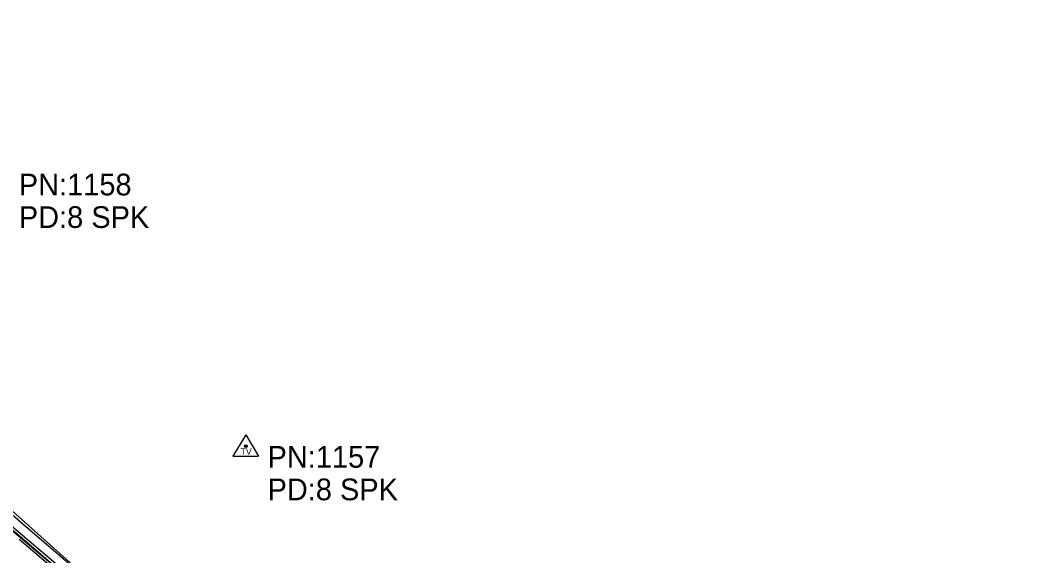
# Model space of a CAD drawing. Extents: x 878399 to 889864, y 1564003 to 1567413.
# Drawn here: x 884685 to 884917.5, y 1565562 to 1565685.6 of the extents above; entities that cross this region are included whole.
import ezdxf

# ---------------------------------------------------------------- set-up
doc = ezdxf.new("R2010")
doc.units = 0
for name, color, linetype in [('S_DITCHLINE', 7, 'Continuous'), ('S_EDGE_CONCRETE', 7, 'Continuous'), ('S_EDGE_PAVEMENT', 7, 'Continuous'), ('S_SECONDARY_CTL', 7, 'Continuous'), ('S_SECONDARY_CTL_ANNOT', 7, 'Continuous'), ('S_SHOULDER', 7, 'Continuous')]:
    doc.layers.add(name, color=color, linetype=linetype)

msp = doc.modelspace()

# ---------------------------------------------------------------- linework, layer by layer
at = {"layer": 'S_DITCHLINE'}
msp.add_lwpolyline([(884703.6, 1565553.91), (884685.15, 1565569.81), (884674.64, 1565578.91)], dxfattribs=at)
at = {"layer": 'S_EDGE_CONCRETE'}
for points in [[(884323.93, 1565880.39), (884362.03, 1565848.01), (884400.08, 1565815.49), (884438.03, 1565782.92), (884475.84, 1565750.35), (884513.92, 1565717.85), (884552.01, 1565685.45), (884589.9, 1565652.9), (884627.72, 1565620.23), (884666.58, 1565587.18), (884704.34, 1565553.44)], [(884321.95, 1565878.07), (884359.86, 1565845.48), (884397.91, 1565812.97), (884436.05, 1565780.63), (884473.97, 1565748.16), (884511.98, 1565715.58), (884549.99, 1565683.11), (884587.82, 1565650.46), (884625.88, 1565618.07), (884664.43, 1565584.66), (884703.02, 1565551.9)]]:
    msp.add_lwpolyline(points, dxfattribs=at)
at = {"layer": 'S_EDGE_PAVEMENT'}
for points in [[(884673.76, 1565575.86), (884685.2, 1565566.15), (884696.63, 1565556.44), (884708.06, 1565546.72), (884719.51, 1565537.03), (884730.93, 1565527.29), (884742.33, 1565517.55), (884753.72, 1565507.79), (884765.12, 1565498.04), (884776.53, 1565488.26), (884787.91, 1565478.49), (884799.29, 1565468.72), (884810.66, 1565458.95), (884822.04, 1565449.18), (884833.38, 1565439.44), (884844.76, 1565429.68), (884856.14, 1565419.92), (884867.5, 1565410.14), (884878.86, 1565400.36), (884890.22, 1565390.58), (884901.62, 1565380.84), (884913.16, 1565370.98), (884924.56, 1565361.24)], [(884684.78, 1565565.87), (884696.21, 1565556.16), (884707.64, 1565546.44), (884719.09, 1565536.75), (884730.51, 1565527.01), (884741.91, 1565517.27), (884753.31, 1565507.51), (884764.7, 1565497.76), (884776.12, 1565487.98), (884787.5, 1565478.21), (884798.87, 1565468.44), (884810.25, 1565458.67), (884821.62, 1565448.9), (884832.97, 1565439.16), (884844.35, 1565429.4), (884855.73, 1565419.63), (884867.09, 1565409.85), (884878.45, 1565400.07), (884889.81, 1565390.29), (884901.21, 1565380.55), (884912.75, 1565370.69), (884924.15, 1565360.95)]]:
    msp.add_lwpolyline(points, dxfattribs=at)
at = {"layer": 'S_SECONDARY_CTL'}
for p, q in [((884737.1, 1565589.94), (884734.09, 1565584.98)), ((884737.1, 1565589.94), (884740.05, 1565584.98)), ((884734.09, 1565584.98), (884740.05, 1565584.98))]:
    msp.add_line(p, q, dxfattribs=at)
for radius in [0.311, 0.183, 0.103]:
    msp.add_circle((884737.1, 1565587.33), radius, dxfattribs=at)
at = {"layer": 'S_SHOULDER'}
msp.add_lwpolyline([(884315.55, 1565882.9), (884321.54, 1565877.6), (884359.45, 1565845), (884397.59, 1565812.6), (884435.73, 1565780.26), (884473.65, 1565747.79), (884511.66, 1565715.22), (884549.66, 1565682.72), (884587.52, 1565650.1), (884625.56, 1565617.69), (884664.18, 1565584.36), (884702.58, 1565551.39), (884704.78, 1565549.31), (884722.81, 1565534.04), (884741.48, 1565517.97), (884779.63, 1565485.61), (884817.88, 1565453.42), (884855.77, 1565420.91), (884891.75, 1565389.81), (884929.91, 1565357.22)], dxfattribs=at)

# ---------------------------------------------------------------- texts
at = {"layer": 'S_SECONDARY_CTL'}
msp.add_text('TV', height=1.5, rotation=360, dxfattribs=at).set_placement((884735.9, 1565585.32))
at = {"layer": 'S_SECONDARY_CTL_ANNOT'}
for s, p in [('PN:1158', (884684.72, 1565645.14)), ('PD:8 SPK', (884684.72, 1565637.64)), ('PN:1157', (884742.1, 1565582.33)), ('PD:8 SPK', (884742.1, 1565574.83))]:
    msp.add_text(s, height=5, dxfattribs=at).set_placement(p)

doc.saveas('drawing.dxf')
